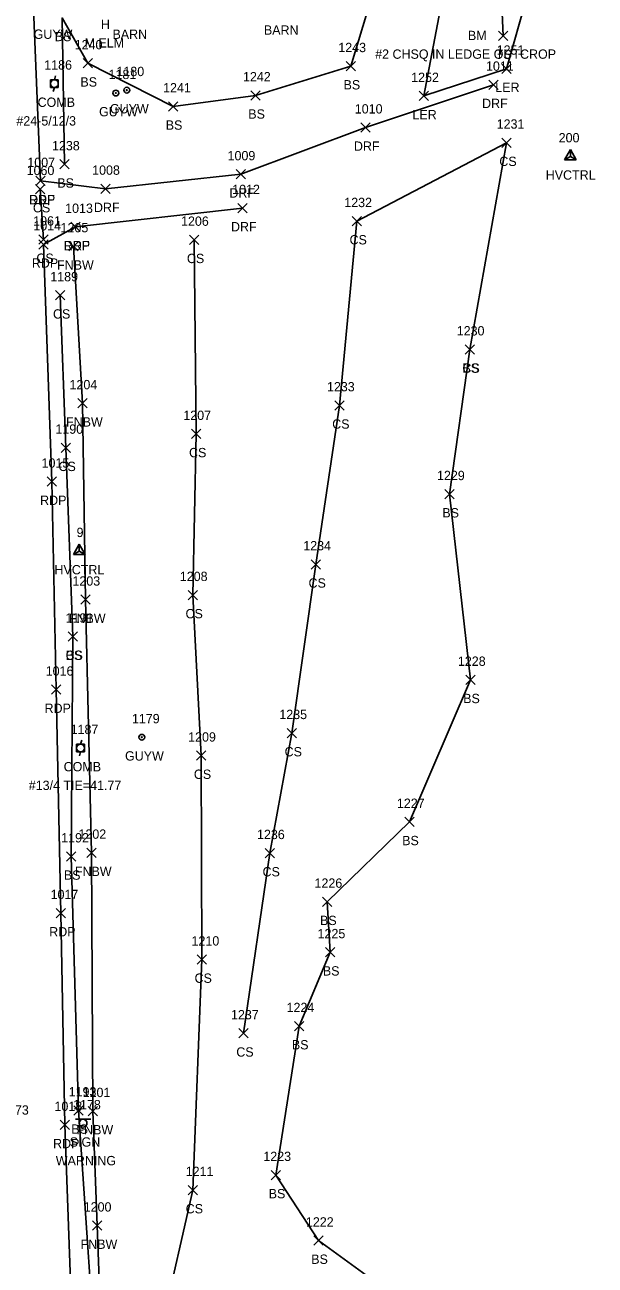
# Model space of a CAD drawing. Extents: x 1609623 to 1616187, y 756677 to 762826.
# Drawn here: x 1610629.1 to 1610751.4, y 761370.1 to 761636.1 of the extents above; entities that cross this region are included whole.
import ezdxf

# ---------------------------------------------------------------- set-up
doc = ezdxf.new("R2010")
doc.units = 0
for name, color, linetype in [('C_A', 7, 'Continuous'), ('C_C', 7, 'Continuous'), ('C_I', 7, 'Continuous'), ('CPSM', 7, 'Continuous'), ('L_A', 7, 'Continuous'), ('L_C', 7, 'Continuous'), ('L_I', 7, 'Continuous'), ('L_TIC', 7, 'Continuous'), ('LARO', 7, 'Continuous'), ('LELB', 7, 'Continuous'), ('LFNC', 7, 'Continuous'), ('P_A', 7, 'Continuous'), ('P_I', 7, 'Continuous'), ('P_TIC', 7, 'Continuous'), ('PET', 7, 'Continuous'), ('R_A', 7, 'Continuous'), ('R_I', 7, 'Continuous'), ('R_TIC', 7, 'Continuous'), ('RDF', 7, 'Continuous'), ('S_A', 7, 'Continuous'), ('S_C', 7, 'Continuous'), ('S_I', 7, 'Continuous'), ('SSGN', 7, 'Continuous'), ('U_A', 7, 'Continuous'), ('U_C', 7, 'Continuous'), ('U_I', 7, 'Continuous'), ('UP', 7, 'Continuous'), ('UPGW', 7, 'Continuous')]:
    doc.layers.add(name, color=color, linetype=linetype)

msp = doc.modelspace()

# ---------------------------------------------------------------- linework, layer by layer
at = {"layer": 'CPSM'}
for p, q in [((1610744.85, 761607.2), (1610746.1, 761609.37)), ((1610744.85, 761607.2), (1610746.1, 761607.92)), ((1610747.35, 761607.2), (1610746.1, 761609.37)), ((1610746.1, 761607.92), (1610746.1, 761609.37)), ((1610746.1, 761607.92), (1610746.1, 761607.92)), ((1610746.1, 761607.92), (1610747.35, 761607.2)), ((1610744.85, 761607.2), (1610747.35, 761607.2)), ((1610639.51, 761522.54), (1610640.76, 761524.71)), ((1610639.51, 761522.54), (1610640.76, 761523.26)), ((1610639.51, 761522.54), (1610642.01, 761522.54)), ((1610642.01, 761522.54), (1610640.76, 761524.71)), ((1610640.76, 761523.26), (1610640.76, 761524.71)), ((1610640.76, 761523.26), (1610640.76, 761523.26)), ((1610640.76, 761523.26), (1610642.01, 761522.54))]:
    msp.add_line(p, q, dxfattribs=at)
at = {"layer": 'L_TIC'}
for points in [[(1610730.65, 761632.79), (1610732.65, 761634.79)], [(1610732.65, 761632.79), (1610730.65, 761634.79)], [(1610641.57, 761626.88), (1610643.57, 761628.88)], [(1610643.57, 761626.88), (1610641.57, 761628.88)], [(1610698, 761626.27), (1610700, 761628.27)], [(1610700, 761626.27), (1610698, 761628.27)], [(1610731.4, 761625.72), (1610733.4, 761627.72)], [(1610733.4, 761625.72), (1610731.4, 761627.72)], [(1610677.57, 761620), (1610679.57, 761622)], [(1610679.57, 761620), (1610677.57, 761622)], [(1610713.63, 761619.87), (1610715.63, 761621.87)], [(1610715.63, 761619.87), (1610713.63, 761621.87)], [(1610659.87, 761617.63), (1610661.87, 761619.63)], [(1610661.87, 761617.63), (1610659.87, 761619.63)], [(1610731.4, 761609.85), (1610733.4, 761611.85)], [(1610733.4, 761609.85), (1610731.4, 761611.85)], [(1610636.62, 761605.21), (1610638.62, 761607.21)], [(1610638.62, 761605.21), (1610636.62, 761607.21)], [(1610631.39, 761599.9), (1610633.39, 761601.9)], [(1610633.39, 761599.9), (1610631.39, 761601.9)], [(1610699.28, 761593.03), (1610701.28, 761595.03)], [(1610701.28, 761593.03), (1610699.28, 761595.03)], [(1610632.13, 761589.07), (1610634.13, 761591.07)], [(1610634.13, 761589.07), (1610632.13, 761591.07)], [(1610638.52, 761587.62), (1610640.52, 761589.62)], [(1610640.52, 761587.62), (1610638.52, 761589.62)], [(1610664.41, 761589.02), (1610666.41, 761591.02)], [(1610666.41, 761589.02), (1610664.41, 761591.02)], [(1610635.69, 761577.12), (1610637.69, 761579.12)], [(1610637.69, 761577.12), (1610635.69, 761579.12)], [(1610723.49, 761565.5), (1610725.49, 761567.5)], [(1610725.49, 761565.5), (1610723.49, 761567.5)], [(1610723.49, 761565.5), (1610725.49, 761567.5)], [(1610725.49, 761565.5), (1610723.49, 761567.5)], [(1610640.45, 761553.96), (1610642.45, 761555.96)], [(1610642.45, 761553.96), (1610640.45, 761555.96)], [(1610695.57, 761553.51), (1610697.57, 761555.51)], [(1610697.57, 761553.51), (1610695.57, 761555.51)], [(1610664.86, 761547.38), (1610666.86, 761549.38)], [(1610666.86, 761547.38), (1610664.86, 761549.38)], [(1610636.87, 761544.42), (1610638.87, 761546.42)], [(1610638.87, 761544.42), (1610636.87, 761546.42)], [(1610719.18, 761534.47), (1610721.18, 761536.47)], [(1610721.18, 761534.47), (1610719.18, 761536.47)], [(1610690.49, 761519.41), (1610692.49, 761521.41)], [(1610692.49, 761519.41), (1610690.49, 761521.41)], [(1610664.11, 761512.83), (1610666.11, 761514.83)], [(1610666.11, 761512.83), (1610664.11, 761514.83)], [(1610641.07, 761511.84), (1610643.07, 761513.84)], [(1610643.07, 761511.84), (1610641.07, 761513.84)], [(1610638.38, 761503.91), (1610640.38, 761505.91)], [(1610640.38, 761503.91), (1610638.38, 761505.91)], [(1610638.38, 761503.91), (1610640.38, 761505.91)], [(1610640.38, 761503.91), (1610638.38, 761505.91)], [(1610723.65, 761494.64), (1610725.65, 761496.64)], [(1610725.65, 761494.64), (1610723.65, 761496.64)], [(1610685.36, 761483.22), (1610687.36, 761485.22)], [(1610687.36, 761483.22), (1610685.36, 761485.22)], [(1610665.9, 761478.39), (1610667.9, 761480.39)], [(1610667.9, 761478.39), (1610665.9, 761480.39)], [(1610710.57, 761464.17), (1610712.57, 761466.17)], [(1610712.57, 761464.17), (1610710.57, 761466.17)], [(1610638.01, 761456.76), (1610640.01, 761458.76)], [(1610640.01, 761456.76), (1610638.01, 761458.76)], [(1610642.36, 761457.55), (1610644.36, 761459.55)], [(1610644.36, 761457.55), (1610642.36, 761459.55)], [(1610680.62, 761457.48), (1610682.62, 761459.48)], [(1610682.62, 761457.48), (1610680.62, 761459.48)], [(1610692.95, 761447.04), (1610694.95, 761449.04)], [(1610694.95, 761447.04), (1610692.95, 761449.04)], [(1610693.56, 761436.21), (1610695.56, 761438.21)], [(1610695.56, 761436.21), (1610693.56, 761438.21)], [(1610666.05, 761434.65), (1610668.05, 761436.65)], [(1610668.05, 761434.65), (1610666.05, 761436.65)], [(1610686.92, 761420.37), (1610688.92, 761422.37)], [(1610688.92, 761420.37), (1610686.92, 761422.37)], [(1610675, 761418.82), (1610677, 761420.82)], [(1610677, 761418.82), (1610675, 761420.82)], [(1610639.62, 761402.28), (1610641.62, 761404.28)], [(1610641.62, 761402.28), (1610639.62, 761404.28)], [(1610642.7, 761402.14), (1610644.7, 761404.14)], [(1610644.7, 761402.14), (1610642.7, 761404.14)], [(1610681.94, 761388.43), (1610683.94, 761390.43)], [(1610683.94, 761388.43), (1610681.94, 761390.43)], [(1610664.15, 761385.2), (1610666.15, 761387.2)], [(1610666.15, 761385.2), (1610664.15, 761387.2)], [(1610643.58, 761377.59), (1610645.58, 761379.59)], [(1610645.58, 761377.59), (1610643.58, 761379.59)], [(1610691.06, 761374.37), (1610693.06, 761376.37)], [(1610693.06, 761374.37), (1610691.06, 761376.37)]]:
    msp.add_lwpolyline(points, dxfattribs=at)
at = {"layer": 'LARO'}
msp.add_lwpolyline([(1610736.14, 761658.02), (1610736.89, 761642.63), (1610732.4, 761626.72), (1610714.63, 761620.87), (1610718.72, 761642.38), (1610727.62, 761660.99)], dxfattribs=at)
at = {"layer": 'LELB'}
for points in [[(1610637.62, 761606.21), (1610637.08, 761637.62), (1610642.57, 761627.88), (1610660.87, 761618.63), (1610678.57, 761621), (1610699, 761627.27), (1610707.62, 761655.9), (1610698.6, 761670.39), (1610707.54, 761687.69), (1610741.15, 761689.82), (1610730.32, 761666.59)], [(1610727.7, 761651.24), (1610731.26, 761643.76), (1610731.65, 761633.79)], [(1610724.49, 761566.5), (1610732.4, 761610.85), (1610700.28, 761594.03), (1610696.57, 761554.51), (1610691.49, 761520.41), (1610686.36, 761484.22), (1610681.62, 761458.48), (1610676, 761419.82)], [(1610632.39, 761600.9), (1610633.13, 761590.07)], [(1610665.41, 761590.02), (1610665.86, 761548.38), (1610665.11, 761513.83), (1610666.9, 761479.39), (1610667.05, 761435.65), (1610665.15, 761386.2), (1610658.62, 761357.61), (1610648.95, 761332.06)], [(1610636.69, 761578.12), (1610637.87, 761545.42), (1610639.38, 761504.91)], [(1610648.95, 761332.06), (1610650.48, 761307.87), (1610655.69, 761276.79), (1610654.41, 761237.62), (1610657.36, 761259), (1610668.14, 761289.99), (1610659.22, 761311.01), (1610678.21, 761341.56), (1610707.76, 761363.95), (1610692.06, 761375.37), (1610682.94, 761389.43), (1610687.92, 761421.37), (1610694.56, 761437.21), (1610693.95, 761448.04), (1610711.57, 761465.17), (1610724.65, 761495.64), (1610720.18, 761535.47), (1610724.49, 761566.5)], [(1610639.38, 761504.91), (1610639.01, 761457.76), (1610640.62, 761403.28), (1610644.99, 761339.38)]]:
    msp.add_lwpolyline(points, dxfattribs=at)
at = {"layer": 'LFNC'}
msp.add_lwpolyline([(1610646.89, 761219.98), (1610646.97, 761255.24), (1610647.11, 761310.95), (1610644.58, 761378.59), (1610643.7, 761403.14), (1610643.36, 761458.55), (1610642.07, 761512.84), (1610641.45, 761554.96), (1610639.52, 761588.62)], dxfattribs=at)
at = {"layer": 'P_TIC'}
for points in [[(1610631.48, 761601.64), (1610633.48, 761603.64)], [(1610633.48, 761601.64), (1610631.48, 761603.64)], [(1610638.94, 761591.79), (1610640.94, 761593.79)], [(1610640.94, 761591.79), (1610638.94, 761593.79)], [(1610632.12, 761588.03), (1610634.12, 761590.03)], [(1610634.12, 761588.03), (1610632.12, 761590.03)], [(1610633.88, 761537.15), (1610635.88, 761539.15)], [(1610635.88, 761537.15), (1610633.88, 761539.15)], [(1610634.83, 761492.54), (1610636.83, 761494.54)], [(1610636.83, 761492.54), (1610634.83, 761494.54)], [(1610635.83, 761444.6), (1610637.83, 761446.6)], [(1610637.83, 761444.6), (1610635.83, 761446.6)], [(1610636.66, 761399.17), (1610638.66, 761401.17)], [(1610638.66, 761399.17), (1610636.66, 761401.17)]]:
    msp.add_lwpolyline(points, dxfattribs=at)
at = {"layer": 'PET'}
for points in [[(1610609.92, 761821.12), (1610621.19, 761822.12), (1610623.98, 761800.55), (1610628.71, 761771.08), (1610628.46, 761733.13), (1610630.54, 761698.27), (1610630.63, 761648.45), (1610632.48, 761602.64)], [(1610639.94, 761592.79), (1610633.12, 761589.03), (1610634.88, 761538.15), (1610635.83, 761493.54), (1610636.83, 761445.6), (1610637.66, 761400.17), (1610639.5, 761348.91), (1610641.24, 761292.52), (1610644.25, 761218.62)]]:
    msp.add_lwpolyline(points, dxfattribs=at)
at = {"layer": 'R_TIC'}
for points in [[(1610728.62, 761622.28), (1610730.62, 761624.28)], [(1610730.62, 761622.28), (1610728.62, 761624.28)], [(1610701.14, 761613.11), (1610703.14, 761615.11)], [(1610703.14, 761613.11), (1610701.14, 761615.11)], [(1610674.43, 761603.07), (1610676.43, 761605.07)], [(1610676.43, 761603.07), (1610674.43, 761605.07)], [(1610631.48, 761601.64), (1610633.48, 761603.64)], [(1610633.48, 761601.64), (1610631.48, 761603.64)], [(1610645.38, 761599.97), (1610647.38, 761601.97)], [(1610647.38, 761599.97), (1610645.38, 761601.97)], [(1610674.76, 761595.83), (1610676.76, 761597.83)], [(1610676.76, 761595.83), (1610674.76, 761597.83)], [(1610638.94, 761591.79), (1610640.94, 761593.79)], [(1610640.94, 761591.79), (1610638.94, 761593.79)]]:
    msp.add_lwpolyline(points, dxfattribs=at)
at = {"layer": 'RDF'}
for points in [[(1610632.48, 761602.64), (1610646.38, 761600.97), (1610675.43, 761604.07), (1610702.14, 761614.11), (1610729.62, 761623.28)], [(1610675.76, 761596.83), (1610639.94, 761592.79)]]:
    msp.add_lwpolyline(points, dxfattribs=at)
at = {"layer": 'SSGN'}
for p, q in [((1610639.94, 761401.38), (1610643.27, 761401.38)), ((1610641.59, 761400.54), (1610641.59, 761400.54))]:
    msp.add_line(p, q, dxfattribs=at)
msp.add_circle((1610641.59, 761400.54), 0.833, dxfattribs=at)
at = {"layer": 'UP'}
for p, q in [((1610634.61, 761622.7), (1610634.61, 761624.36)), ((1610634.61, 761624.36), (1610636.27, 761624.36)), ((1610635.69, 761625.2), (1610635.44, 761624.36)), ((1610635.44, 761623.53), (1610635.44, 761623.53)), ((1610636.27, 761624.36), (1610636.27, 761622.7)), ((1610636.27, 761622.7), (1610634.61, 761622.7)), ((1610635.19, 761621.86), (1610635.44, 761622.7)), ((1610641.29, 761482.67), (1610641.04, 761481.84)), ((1610640.2, 761480.17), (1610640.2, 761481.84)), ((1610640.2, 761481.84), (1610641.87, 761481.84)), ((1610641.87, 761480.17), (1610640.2, 761480.17)), ((1610640.79, 761479.34), (1610641.04, 761480.17)), ((1610641.04, 761481.01), (1610641.04, 761481.01)), ((1610641.87, 761481.84), (1610641.87, 761480.17))]:
    msp.add_line(p, q, dxfattribs=at)
for centre in [(1610635.44, 761623.53), (1610641.04, 761481.01)]:
    msp.add_circle(centre, 0.833, dxfattribs=at)
at = {"layer": 'UPGW'}
for centre, radius in [((1610648.61, 761621.5), 0.625), ((1610648.61, 761621.5), 0.0833), ((1610650.95, 761622.13), 0.625), ((1610650.95, 761622.13), 0.0833), ((1610654.19, 761483.32), 0.625), ((1610654.19, 761483.32), 0.0833)]:
    msp.add_circle(centre, radius, dxfattribs=at)

# ---------------------------------------------------------------- texts
at = {"layer": 'C_A'}
for s, p in [('BM', (1610724.11, 761632.85)), ('HVCTRL', (1610740.79, 761602.92)), ('HVCTRL', (1610635.45, 761518.26))]:
    msp.add_text(s, height=2, dxfattribs=at).set_placement(p)
at = {"layer": 'C_C'}
msp.add_text('#2 CHSQ IN LEDGE OUTCROP', height=2, dxfattribs=at).set_placement((1610704.22, 761628.85))
at = {"layer": 'C_I'}
for s, p in [('200', (1610743.57, 761610.92)), ('9', (1610640.19, 761526.26))]:
    msp.add_text(s, height=2, dxfattribs=at).set_placement(p)
at = {"layer": 'L_A'}
for s, p in [('H', (1610645.42, 761635.26)), ('BS', (1610635.52, 761632.62)), ('BARN', (1610647.89, 761633.11)), ('BARN', (1610680.36, 761634.01)), ('TS', (1610730.05, 761628.79)), ('BS', (1610641.01, 761622.88)), ('BS', (1610697.44, 761622.27)), ('LER', (1610729.98, 761621.72)), ('BS', (1610659.31, 761613.63)), ('BS', (1610677.01, 761616)), ('LER', (1610712.21, 761615.87)), ('CS', (1610730.84, 761605.85)), ('BS', (1610636.06, 761601.21)), ('CS', (1610630.83, 761595.9)), ('CS', (1610698.72, 761589.03)), ('CS', (1610631.57, 761585.07)), ('CS', (1610663.85, 761585.02)), ('FNBW', (1610636, 761583.62)), ('CS', (1610635.13, 761573.12)), ('CS', (1610722.93, 761561.5)), ('BS', (1610722.93, 761561.5)), ('FNBW', (1610637.93, 761549.96)), ('CS', (1610695.01, 761549.51)), ('CS', (1610664.3, 761543.38)), ('CS', (1610636.31, 761540.42)), ('BS', (1610718.62, 761530.47)), ('CS', (1610689.93, 761515.41)), ('FNBW', (1610638.54, 761507.84)), ('CS', (1610663.55, 761508.83)), ('CS', (1610637.83, 761499.91)), ('BS', (1610637.83, 761499.91)), ('BS', (1610723.09, 761490.64)), ('CS', (1610684.8, 761479.22)), ('CS', (1610665.34, 761474.39)), ('BS', (1610710.01, 761460.17)), ('BS', (1610637.46, 761452.76)), ('FNBW', (1610639.83, 761453.55)), ('CS', (1610680.07, 761453.48)), ('BS', (1610692.39, 761443.04)), ('CS', (1610665.49, 761430.65)), ('BS', (1610693, 761432.21)), ('CS', (1610674.44, 761414.82)), ('BS', (1610686.36, 761416.37)), ('BS', (1610639.06, 761398.28)), ('FNBW', (1610640.17, 761398.14)), ('BS', (1610681.38, 761384.43)), ('CS', (1610663.59, 761381.2)), ('FNBW', (1610641.05, 761373.59)), ('BS', (1610690.51, 761370.37))]:
    msp.add_text(s, height=2, dxfattribs=at).set_placement(p)
at = {"layer": 'L_C'}
msp.add_text('M.ELM', height=2, dxfattribs=at).set_placement((1610641.9, 761631.26))
at = {"layer": 'L_I'}
for s, p in [('1240', (1610639.79, 761630.88)), ('1243', (1610696.31, 761630.27)), ('1251', (1610730.27, 761629.72)), ('1241', (1610658.74, 761621.63)), ('1242', (1610675.87, 761624)), ('1252', (1610711.94, 761623.87)), ('1231', (1610730.27, 761613.85)), ('1238', (1610634.92, 761609.21)), ('1060', (1610629.48, 761603.9)), ('1232', (1610697.59, 761597.03)), ('1061', (1610630.88, 761593.07)), ('1206', (1610662.59, 761593.02)), ('1205', (1610636.75, 761591.62)), ('1189', (1610634.55, 761581.12)), ('1230', (1610721.71, 761569.5)), ('1230', (1610721.71, 761569.5)), ('1204', (1610638.68, 761557.96)), ('1233', (1610693.88, 761557.51)), ('1207', (1610663.08, 761551.38)), ('1190', (1610635.65, 761548.42)), ('1229', (1610717.48, 761538.47)), ('1234', (1610688.8, 761523.41)), ('1203', (1610639.3, 761515.84)), ('1208', (1610662.33, 761516.83)), ('1191', (1610637.83, 761507.91)), ('1191', (1610637.83, 761507.91)), ('1228', (1610721.96, 761498.64)), ('1235', (1610683.67, 761487.22)), ('1209', (1610664.12, 761482.39)), ('1227', (1610708.88, 761468.17)), ('1192', (1610636.89, 761460.76)), ('1202', (1610640.59, 761461.55)), ('1236', (1610678.88, 761461.48)), ('1226', (1610691.21, 761451.04)), ('1210', (1610664.84, 761438.65)), ('1225', (1610691.87, 761440.21)), ('1237', (1610673.3, 761422.82)), ('1224', (1610685.22, 761424.37)), ('1193', (1610638.49, 761406.28)), ('1201', (1610641.49, 761406.14)), ('1223', (1610680.24, 761392.43)), ('1211', (1610663.59, 761389.2)), ('1200', (1610641.72, 761381.59)), ('1222', (1610689.37, 761378.37))]:
    msp.add_text(s, height=2, dxfattribs=at).set_placement(p)
at = {"layer": 'P_A'}
for p in [(1610629.97, 761597.64), (1610637.43, 761587.79), (1610630.6, 761584.03), (1610632.37, 761533.15), (1610633.32, 761488.54), (1610634.32, 761440.6), (1610635.15, 761395.17)]:
    msp.add_text('RDP', height=2, dxfattribs=at).set_placement(p)
at = {"layer": 'P_I'}
for s, p in [('1007', (1610629.63, 761605.64)), ('1013', (1610637.74, 761595.79)), ('1014', (1610630.91, 761592.03)), ('1015', (1610632.68, 761541.15)), ('1016', (1610633.57, 761496.54)), ('1017', (1610634.62, 761448.6)), ('1173', (1610623.99, 761402.37)), ('1018', (1610635.45, 761403.17))]:
    msp.add_text(s, height=2, dxfattribs=at).set_placement(p)
at = {"layer": 'R_A'}
for p in [(1610727.15, 761618.28), (1610699.67, 761609.11), (1610630.02, 761597.64), (1610672.96, 761599.07), (1610643.92, 761595.97), (1610673.3, 761591.83), (1610637.48, 761587.79)]:
    msp.add_text('DRF', height=2, dxfattribs=at).set_placement(p)
at = {"layer": 'R_I'}
for s, p in [('1011', (1610727.98, 761626.28)), ('1010', (1610699.85, 761617.11)), ('1007', (1610629.63, 761605.64)), ('1009', (1610672.57, 761607.07)), ('1008', (1610643.53, 761603.97)), ('1012', (1610673.56, 761599.83)), ('1013', (1610637.74, 761595.79))]:
    msp.add_text(s, height=2, dxfattribs=at).set_placement(p)
at = {"layer": 'S_A'}
msp.add_text('SIGN', height=2, dxfattribs=at).set_placement((1610638.72, 761395.52))
at = {"layer": 'S_C'}
msp.add_text('WARNING', height=2, dxfattribs=at).set_placement((1610635.73, 761391.52))
at = {"layer": 'S_I'}
msp.add_text('1178', height=2, dxfattribs=at).set_placement((1610639.44, 761403.52))
at = {"layer": 'U_A'}
for s, p in [('GUYW', (1610630.98, 761633.12)), ('COMB', (1610631.83, 761618.53)), ('GUYW', (1610645.01, 761616.5)), ('GUYW', (1610647.34, 761617.13)), ('GUYW', (1610650.58, 761478.32)), ('COMB', (1610637.42, 761476.01))]:
    msp.add_text(s, height=2, dxfattribs=at).set_placement(p)
at = {"layer": 'U_C'}
for s, p in [('#24-5/12/3', (1610627.28, 761614.53)), ('#13/4 TIE=41.77', (1610629.94, 761472.01))]:
    msp.add_text(s, height=2, dxfattribs=at).set_placement(p)
at = {"layer": 'U_I'}
for s, p in [('1186', (1610633.26, 761626.53)), ('1181', (1610647.05, 761624.5)), ('1180', (1610648.74, 761625.13)), ('1179', (1610652.06, 761486.32)), ('1187', (1610638.91, 761484.01))]:
    msp.add_text(s, height=2, dxfattribs=at).set_placement(p)

doc.saveas('drawing.dxf')
